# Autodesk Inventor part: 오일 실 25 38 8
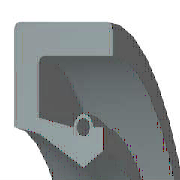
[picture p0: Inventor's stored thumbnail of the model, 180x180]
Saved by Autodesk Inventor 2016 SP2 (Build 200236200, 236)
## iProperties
IsCustomPart: 1
Created: 2012-02
Part Number: 오일 실 25 38 8
Material: 고무
Description: 오일-실
Document SubType Name: Modeling
Standard: KS B 2804
Designer: mduedu
Standards Organization: KS
Language: ko-KR
Size Designation: S - 25 38 8
Categories: <MemberInstance><Categories><Category DisplayName="샤프트 부품" InternalName="7f7aeb1f-a693-4053-b835-cee3144e0d98" Mnemonic="SHFT"><Category DisplayName="실링" Intern
Density: 0.93 g/cm^3
Appearance: 고무 - 검은색 - 버전 1.1
Author: mduedu
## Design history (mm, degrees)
revolve "본체" stored, may be unused: angle "d17" = 90 deg
revolve "스프링1" stored, may be unused: angle "d18" = 90 deg
body "Solid1"
sketch "스케치1"
  geometry: L1 (0, 19)-(8, 19); L2 (8, 19)-(8, 17.75); L3 (8, 17.75)-(1.75, 17.75); L4 (0, 19)-(0, 14.6); L5 (0, 14.6)-(1.75, 14.25); L6 (1.75, 14.25)-(4.9, 12.5); L7 (4.9, 12.5)-(0, 12.5); L8 (6.3, 13.375)-(6.3, 14.6); L9 (0, 0)-(9.586, 0) reference; L10 (4.9, 12.5)-(6.3, 13.375); L11 (0, 18)-(0, -3) reference; L12 (-1.917, 0)-(11.503, 0) reference; L13 (4.2, 14.6)-(1.75, 15.09); L14 (1.75, 15.09)-(1.75, 17.75); L15 (6.3, 14.6)-(5.6, 14.6); C1 r 0.455 at (4.9, 14.6); A1 r 0.7 centre (4.9, 14.6) between (5.6, 14.6) and (4.2, 14.6)
  constraints: 26 end point, 5 horizontal alignment, 4 perpendicular, 2 centre point, 2 collinear, 2 horizontal, 2 parallel, 2 point on circle, 2 point on line, 2 vertical alignment, 1 coincident
  dimensions: "d0" = 38 diameter of L1 L9 (= SD2); "d1" = 26.75 diameter of L8.start L9 (= ABDM); "d2" = 1.25 distance of L1.end L2.end (computed from SD); "d3" = 0.91 diameter of C1 (= SPDI); "d4" = 1.4 diameter of A1 (= SPDA); "d5" = 25 diameter of L6.end L9 (= NND); "d6" = 28.5 diameter of L5.end L9 (= TKDM); "d7" = 29.2 diameter of L4.end L9 (= HLDM); "d8" = 4.9 distance from line of C1.centre L4 (= SPDST); "d9" = 6.3 distance between parallel lines of L8 L4 (= SDI); "d10" = 8 distance between parallel lines of L2 L4 (= SWDT); "d12" = 1.75 distance between parallel lines of L14 L4 (= SD)
fillet "모깎기1" dims "d11" = 0.5 (= RR)
other parameters: "SD2" = 38 [user parameter; used in 1 equation term], "SWDT" = 8 [user parameter; used in 1 equation term], "RR" = 0.5 [user parameter; used in 1 equation term], "SD" = 1.75 [user parameter; used in 2 equation terms], "NND" = 25 [user parameter; used in 1 equation term], "SPDA" = 1.4 [user parameter; used in 1 equation term], "SPDI" = 0.91 [user parameter; used in 1 equation term], "TKDM" = 28.5 [user parameter; used in 1 equation term], "HLDM" = 29.2 [user parameter; used in 1 equation term], "ABDM" = 26.75 [user parameter; used in 1 equation term], "SDI" = 6.3 [user parameter; used in 1 equation term], "SPDST" = 4.9 [user parameter; used in 1 equation term], "d13" = 0, "d14" = 0, "d15" = 0, "LAB" = 0.35 [user parameter]
